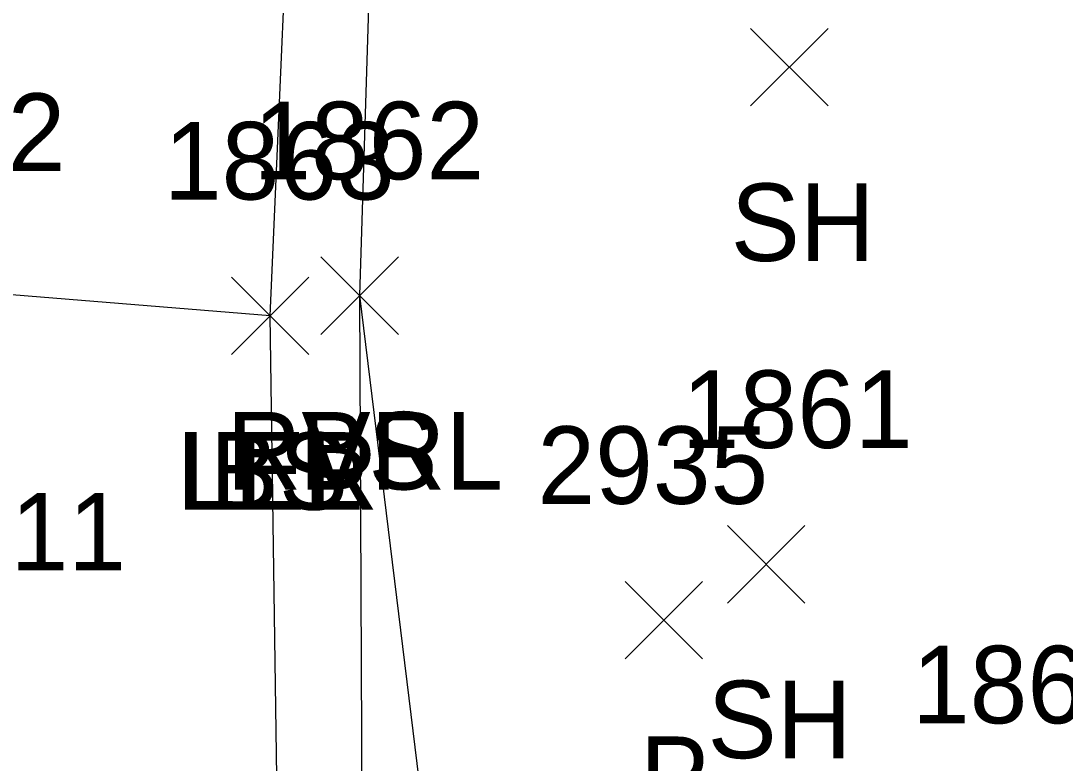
# Model space of a CAD drawing. Extents: x 1638344 to 1639591, y 610835 to 612202.
# Drawn here: x 1638713.96 to 1638740.88, y 611654.31 to 611673.45 of the extents above; entities that cross this region are included whole.
import ezdxf

# ---------------------------------------------------------------- set-up
doc = ezdxf.new("R2010")
doc.units = 0
for name, color, linetype in [('D_A', 7, 'Continuous'), ('D_I', 7, 'Continuous'), ('D_TIC', 7, 'Continuous'), ('L_A', 7, 'Continuous'), ('L_I', 7, 'Continuous'), ('L_TIC', 7, 'Continuous'), ('LARO', 7, 'Continuous'), ('LAWE', 7, 'Continuous'), ('LELB', 7, 'Continuous')]:
    doc.layers.add(name, color=color, linetype=linetype)

msp = doc.modelspace()

# ---------------------------------------------------------------- linework, layer by layer
at = {"layer": 'D_TIC'}
for points in [[(1638729.538, 611656.996), (1638731.538, 611658.996)], [(1638731.538, 611656.996), (1638729.538, 611658.996)]]:
    msp.add_lwpolyline(points, dxfattribs=at)
at = {"layer": 'L_TIC'}
for points in [[(1638732.774, 611671.259), (1638734.774, 611673.259)], [(1638734.774, 611671.259), (1638732.774, 611673.259)], [(1638721.694, 611665.366), (1638723.694, 611667.366)], [(1638723.694, 611665.366), (1638721.694, 611667.366)], [(1638721.694, 611665.366), (1638723.694, 611667.366)], [(1638723.694, 611665.366), (1638721.694, 611667.366)], [(1638719.387, 611664.845), (1638721.387, 611666.845)], [(1638721.387, 611664.845), (1638719.387, 611666.845)], [(1638719.387, 611664.845), (1638721.387, 611666.845)], [(1638721.387, 611664.845), (1638719.387, 611666.845)], [(1638719.387, 611664.845), (1638721.387, 611666.845)], [(1638721.387, 611664.845), (1638719.387, 611666.845)], [(1638732.176, 611658.437), (1638734.176, 611660.437)], [(1638734.176, 611658.437), (1638732.176, 611660.437)]]:
    msp.add_lwpolyline(points, dxfattribs=at)
at = {"layer": 'LARO'}
for points in [[(1638720.387, 611665.845), (1638721.028, 611680.57), (1638719.094, 611692.553), (1638724.927, 611710.662), (1638728.568, 611713.859), (1638729.448, 611725.986)], [(1638720.387, 611665.845), (1638711.282, 611666.582), (1638703.001, 611660.659), (1638697.535, 611657.21), (1638690.762, 611655.965), (1638683.724, 611657.237), (1638681.669, 611658.631)]]:
    msp.add_lwpolyline(points, dxfattribs=at)
at = {"layer": 'LAWE'}
msp.add_lwpolyline([(1638671.011, 611601.41), (1638687.934, 611612.159), (1638702.816, 611621.305), (1638722.828, 611637.898), (1638722.694, 611666.366), (1638723.119, 611679.868), (1638719.094, 611692.553), (1638717.187, 611697.341), (1638711.048, 611700.649), (1638718.685, 611716.114), (1638719.359, 611723.061), (1638714.323, 611734.571), (1638714.704, 611747.214), (1638712.56, 611755.84), (1638714.994, 611761.22), (1638711.865, 611767.72), (1638710.522, 611777.786), (1638714.936, 611789.326), (1638716.942, 611806.826), (1638715.698, 611824.36)], dxfattribs=at)
at = {"layer": 'LELB'}
for points in [[(1638680.248, 611562.888), (1638697.03, 611576.026), (1638709.984, 611594.301), (1638726.456, 611635.702), (1638722.694, 611666.366)], [(1638669.405, 611602.331), (1638686.193, 611614.735), (1638699.594, 611624.943), (1638720.779, 611638.494), (1638720.387, 611665.845)]]:
    msp.add_lwpolyline(points, dxfattribs=at)

# ---------------------------------------------------------------- texts
at = {"layer": 'D_A'}
msp.add_text('P', height=2, dxfattribs=at).set_placement((1638729.916, 611652.996))
at = {"layer": 'D_I'}
msp.add_text('2935', height=2, dxfattribs=at).set_placement((1638727.278, 611660.996))
at = {"layer": 'L_A'}
for s, p in [('SH', (1638732.262, 611667.259)), ('RVRL', (1638719.261, 611661.366)), ('BS', (1638721.135, 611661.366)), ('LER', (1638717.969, 611660.845)), ('LEL', (1638718.024, 611660.845)), ('BS', (1638718.828, 611660.845)), ('SH', (1638731.664, 611654.437))]:
    msp.add_text(s, height=2, dxfattribs=at).set_placement(p)
at = {"layer": 'L_I'}
for s, p in [('1912', (1638709.156, 611669.582)), ('1862', (1638719.953, 611669.366)), ('1862', (1638719.953, 611669.366)), ('1863', (1638717.646, 611668.845)), ('1863', (1638717.646, 611668.845)), ('1863', (1638717.646, 611668.845)), ('1861', (1638731.002, 611662.437)), ('1911', (1638710.717, 611659.28)), ('1860', (1638736.936, 611655.336))]:
    msp.add_text(s, height=2, dxfattribs=at).set_placement(p)

doc.saveas('drawing.dxf')
